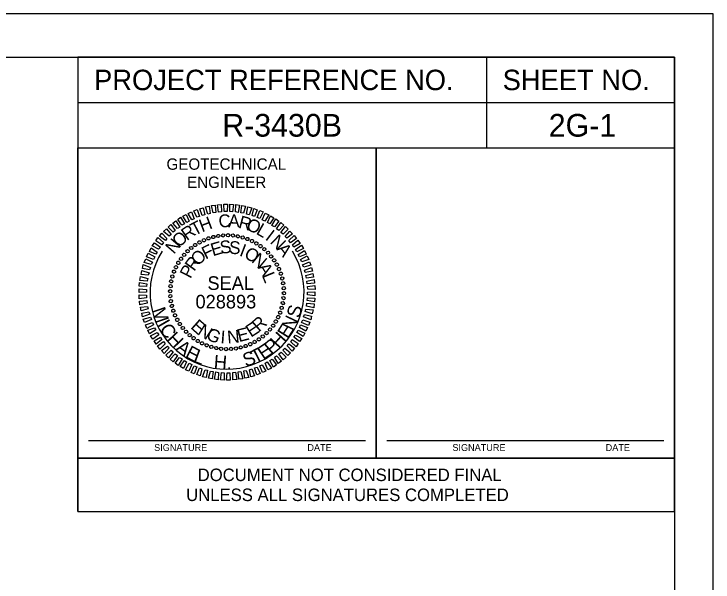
# Model space of a CAD drawing. Extents: x 1252282 to 1252638, y 733735 to 733845.
# Drawn here: x 1252606.82 to 1252637.98, y 733819.19 to 733844.5 of the extents above; entities that cross this region are included whole.
import ezdxf

# ---------------------------------------------------------------- set-up
doc = ezdxf.new("R2010")
doc.units = 0
for name, color, linetype in [('Default', 7, 'Continuous'), ('Scratch_Level_0', 7, 'Continuous'), ('Sheet Plot Border Outside CELL', 7, 'Continuous'), ('Sheet Professional Seal CELL', 7, 'Continuous'), ('Sheet Sticker Exception Certification CELL', 7, 'Continuous'), ('Sheet Typical CELL', 7, 'Continuous')]:
    doc.layers.add(name, color=color, linetype=linetype)

msp = doc.modelspace()

# ---------------------------------------------------------------- linework, layer by layer
at = {"layer": 'Scratch_Level_0'}
msp.add_line((1252637.975, 733844.502), (1252637.975, 733844.502), dxfattribs=at)
msp.add_ellipse((1252616.319, 733832.107), major_axis=(2.279, 2.58), ratio=0.993455, start_param=1.731198, end_param=5.992706, dxfattribs=at)
at = {"layer": 'Sheet Plot Border Outside CELL'}
msp.add_lwpolyline([(1252467.333, 733734.502), (1252637.975, 733734.502), (1252637.975, 733844.502), (1252467.333, 733844.502)], close=True, dxfattribs=at)
at = {"layer": 'Sheet Professional Seal CELL'}
for p, q in [((1252615.288, 733834.427), (1252615.288, 733834.427)), ((1252615.49, 733834.507), (1252615.49, 733834.507)), ((1252615.702, 733834.568), (1252615.702, 733834.568)), ((1252615.925, 733834.609), (1252615.925, 733834.609)), ((1252616.142, 733834.639), (1252616.142, 733834.639)), ((1252616.364, 733834.644), (1252616.364, 733834.644)), ((1252616.587, 733834.629), (1252616.587, 733834.629)), ((1252616.804, 733834.593), (1252616.804, 733834.593)), ((1252617.016, 733834.548), (1252617.016, 733834.548)), ((1252617.229, 733834.477), (1252617.229, 733834.477)), ((1252617.431, 733834.386), (1252617.431, 733834.386)), ((1252614.722, 733834.083), (1252614.722, 733834.083)), ((1252614.898, 733834.209), (1252614.898, 733834.209)), ((1252615.091, 733834.326), (1252615.091, 733834.326)), ((1252617.628, 733834.285), (1252617.628, 733834.285)), ((1252617.81, 733834.159), (1252617.81, 733834.159)), ((1252614.403, 733833.775), (1252614.403, 733833.775)), ((1252614.555, 733833.931), (1252614.555, 733833.931)), ((1252617.987, 733834.022), (1252617.987, 733834.022)), ((1252618.143, 733833.871), (1252618.143, 733833.871)), ((1252614.267, 733833.598), (1252614.267, 733833.598)), ((1252618.295, 733833.704), (1252618.295, 733833.704)), ((1252618.421, 733833.527), (1252618.421, 733833.527)), ((1252614.039, 733833.219), (1252614.039, 733833.219)), ((1252614.14, 733833.416), (1252614.14, 733833.416)), ((1252618.538, 733833.335), (1252618.538, 733833.335)), ((1252618.639, 733833.138), (1252618.639, 733833.138)), ((1252613.877, 733832.804), (1252613.877, 733832.804)), ((1252613.948, 733833.016), (1252613.948, 733833.016)), ((1252618.72, 733832.936), (1252618.72, 733832.936)), ((1252613.832, 733832.592), (1252613.832, 733832.592)), ((1252618.78, 733832.723), (1252618.78, 733832.723)), ((1252618.821, 733832.501), (1252618.821, 733832.501)), ((1252613.797, 733832.374), (1252613.797, 733832.374)), ((1252618.851, 733832.283), (1252618.851, 733832.283)), ((1252613.781, 733832.152), (1252613.781, 733832.152)), ((1252613.786, 733831.93), (1252613.786, 733831.93)), ((1252618.856, 733832.061), (1252618.856, 733832.061)), ((1252613.817, 733831.712), (1252613.817, 733831.712)), ((1252618.806, 733831.621), (1252618.806, 733831.621)), ((1252618.841, 733831.839), (1252618.841, 733831.839)), ((1252613.857, 733831.49), (1252613.857, 733831.49)), ((1252613.918, 733831.278), (1252613.918, 733831.278)), ((1252618.76, 733831.409), (1252618.76, 733831.409)), ((1252613.999, 733831.075), (1252613.999, 733831.075)), ((1252618.598, 733830.995), (1252618.598, 733830.995)), ((1252618.689, 733831.197), (1252618.689, 733831.197)), ((1252614.1, 733830.878), (1252614.1, 733830.878)), ((1252614.216, 733830.686), (1252614.216, 733830.686)), ((1252618.497, 733830.797), (1252618.497, 733830.797)), ((1252614.342, 733830.509), (1252614.342, 733830.509)), ((1252614.494, 733830.343), (1252614.494, 733830.343)), ((1252618.234, 733830.439), (1252618.234, 733830.439)), ((1252618.371, 733830.615), (1252618.371, 733830.615)), ((1252614.651, 733830.191), (1252614.651, 733830.191)), ((1252614.828, 733830.054), (1252614.828, 733830.054)), ((1252617.739, 733830.004), (1252617.739, 733830.004)), ((1252617.916, 733830.13), (1252617.916, 733830.13)), ((1252618.083, 733830.282), (1252618.083, 733830.282)), ((1252615.01, 733829.928), (1252615.01, 733829.928)), ((1252615.207, 733829.827), (1252615.207, 733829.827)), ((1252615.409, 733829.736), (1252615.409, 733829.736)), ((1252617.148, 733829.706), (1252617.148, 733829.706)), ((1252617.35, 733829.787), (1252617.35, 733829.787)), ((1252617.547, 733829.888), (1252617.547, 733829.888)), ((1252615.621, 733829.665), (1252615.621, 733829.665)), ((1252615.834, 733829.62), (1252615.834, 733829.62)), ((1252616.051, 733829.584), (1252616.051, 733829.584)), ((1252616.273, 733829.569), (1252616.273, 733829.569)), ((1252616.496, 733829.574), (1252616.496, 733829.574)), ((1252616.713, 733829.605), (1252616.713, 733829.605)), ((1252616.935, 733829.645), (1252616.935, 733829.645))]:
    msp.add_line(p, q, dxfattribs=at)
for points in [[(1252615.459, 733835.589), (1252615.353, 733835.908), (1252615.525, 733835.943), (1252615.566, 733835.614)], [(1252615.702, 733835.645), (1252615.621, 733835.968), (1252615.788, 733835.983), (1252615.823, 733835.66)], [(1252615.945, 733835.675), (1252615.889, 733835.999), (1252616.061, 733836.019), (1252616.066, 733835.69)], [(1252616.197, 733835.7), (1252616.172, 733836.029), (1252616.339, 733836.024), (1252616.319, 733835.695)], [(1252616.44, 733835.695), (1252616.44, 733836.024), (1252616.607, 733836.019), (1252616.561, 733835.69)], [(1252616.693, 733835.68), (1252616.713, 733836.009), (1252616.88, 733835.978), (1252616.814, 733835.66)], [(1252616.935, 733835.64), (1252616.981, 733835.963), (1252617.148, 733835.938), (1252617.057, 733835.625)], [(1252617.193, 733835.584), (1252617.244, 733835.913), (1252617.416, 733835.872), (1252617.299, 733835.559)], [(1252614.747, 733835.336), (1252614.585, 733835.619), (1252614.742, 733835.69), (1252614.858, 733835.382)], [(1252614.969, 733835.443), (1252614.838, 733835.736), (1252614.989, 733835.796), (1252615.096, 733835.473)], [(1252615.217, 733835.523), (1252615.101, 733835.827), (1252615.257, 733835.872), (1252615.323, 733835.559)], [(1252617.436, 733835.518), (1252617.512, 733835.832), (1252617.668, 733835.781), (1252617.542, 733835.483)], [(1252617.663, 733835.427), (1252617.78, 733835.746), (1252617.921, 733835.685), (1252617.78, 733835.392)], [(1252617.891, 733835.331), (1252618.017, 733835.63), (1252618.174, 733835.559), (1252618.002, 733835.276)], [(1252614.307, 733835.089), (1252614.12, 733835.347), (1252614.251, 733835.443), (1252614.418, 733835.149)], [(1252614.529, 733835.215), (1252614.342, 733835.488), (1252614.499, 733835.569), (1252614.625, 733835.276)], [(1252618.123, 733835.215), (1252618.26, 733835.503), (1252618.411, 733835.417), (1252618.219, 733835.154)], [(1252618.32, 733835.079), (1252618.497, 733835.372), (1252618.629, 733835.266), (1252618.432, 733835.018)], [(1252613.913, 733834.78), (1252613.69, 733835.003), (1252613.812, 733835.124), (1252614.009, 733834.851)], [(1252614.115, 733834.937), (1252613.898, 733835.18), (1252614.034, 733835.286), (1252614.211, 733835.003)], [(1252618.528, 733834.927), (1252618.715, 733835.205), (1252618.846, 733835.094), (1252618.624, 733834.856)], [(1252618.72, 733834.77), (1252618.927, 733835.033), (1252619.048, 733834.912), (1252618.816, 733834.694)], [(1252613.569, 733834.411), (1252613.306, 733834.609), (1252613.417, 733834.74), (1252613.64, 733834.502)], [(1252613.746, 733834.604), (1252613.488, 733834.811), (1252613.615, 733834.927), (1252613.827, 733834.684)], [(1252618.902, 733834.593), (1252619.119, 733834.831), (1252619.24, 733834.71), (1252618.977, 733834.513)], [(1252613.417, 733834.219), (1252613.144, 733834.391), (1252613.241, 733834.538), (1252613.483, 733834.315)], [(1252619.079, 733834.411), (1252619.311, 733834.639), (1252619.417, 733834.502), (1252619.149, 733834.31)], [(1252619.23, 733834.214), (1252619.478, 733834.427), (1252619.574, 733834.28), (1252619.291, 733834.118)], [(1252613.144, 733833.8), (1252612.856, 733833.926), (1252612.932, 733834.083), (1252613.205, 733833.896)], [(1252613.266, 733834.017), (1252612.983, 733834.169), (1252613.084, 733834.31), (1252613.347, 733834.108)], [(1252619.362, 733834.007), (1252619.63, 733834.199), (1252619.726, 733834.048), (1252619.432, 733833.906)], [(1252613.043, 733833.567), (1252612.73, 733833.684), (1252612.806, 733833.84), (1252613.094, 733833.679)], [(1252619.493, 733833.785), (1252619.776, 733833.962), (1252619.842, 733833.805), (1252619.554, 733833.689)], [(1252612.942, 733833.345), (1252612.629, 733833.436), (1252612.695, 733833.593), (1252612.998, 733833.451)], [(1252619.594, 733833.567), (1252619.892, 733833.719), (1252619.958, 733833.557), (1252619.645, 733833.456)], [(1252619.685, 733833.33), (1252619.993, 733833.461), (1252620.049, 733833.304), (1252619.736, 733833.224)], [(1252612.866, 733833.102), (1252612.553, 733833.168), (1252612.588, 733833.335), (1252612.907, 733833.208)], [(1252619.766, 733833.087), (1252620.089, 733833.203), (1252620.12, 733833.037), (1252619.801, 733832.981)], [(1252612.76, 733832.602), (1252612.437, 733832.632), (1252612.457, 733832.804), (1252612.786, 733832.723)], [(1252612.801, 733832.86), (1252612.487, 733832.9), (1252612.523, 733833.072), (1252612.841, 733832.966)], [(1252619.827, 733832.845), (1252620.145, 733832.941), (1252620.175, 733832.769), (1252619.857, 733832.738)], [(1252612.735, 733832.359), (1252612.407, 733832.369), (1252612.417, 733832.536), (1252612.745, 733832.481)], [(1252619.872, 733832.602), (1252620.201, 733832.673), (1252620.216, 733832.501), (1252619.892, 733832.481)], [(1252612.73, 733832.107), (1252612.401, 733832.091), (1252612.401, 733832.263), (1252612.73, 733832.228)], [(1252619.902, 733832.359), (1252620.231, 733832.4), (1252620.241, 733832.228), (1252619.913, 733832.238)], [(1252612.735, 733831.854), (1252612.407, 733831.813), (1252612.396, 733831.985), (1252612.725, 733831.975)], [(1252619.908, 733832.107), (1252620.236, 733832.122), (1252620.236, 733831.95), (1252619.908, 733831.985)], [(1252612.765, 733831.611), (1252612.437, 733831.54), (1252612.422, 733831.712), (1252612.745, 733831.733)], [(1252619.877, 733831.611), (1252620.201, 733831.581), (1252620.18, 733831.409), (1252619.852, 733831.49)], [(1252619.902, 733831.854), (1252620.231, 733831.844), (1252620.221, 733831.677), (1252619.892, 733831.733)], [(1252612.811, 733831.369), (1252612.492, 733831.273), (1252612.462, 733831.444), (1252612.781, 733831.475)], [(1252619.837, 733831.353), (1252620.15, 733831.313), (1252620.115, 733831.141), (1252619.796, 733831.247)], [(1252612.872, 733831.126), (1252612.548, 733831.01), (1252612.518, 733831.177), (1252612.836, 733831.232)], [(1252612.952, 733830.883), (1252612.644, 733830.752), (1252612.588, 733830.909), (1252612.902, 733830.989)], [(1252619.771, 733831.111), (1252620.084, 733831.045), (1252620.049, 733830.878), (1252619.731, 733831.005)], [(1252613.043, 733830.646), (1252612.745, 733830.494), (1252612.679, 733830.656), (1252612.993, 733830.757)], [(1252619.594, 733830.646), (1252619.908, 733830.53), (1252619.832, 733830.373), (1252619.544, 733830.535)], [(1252619.695, 733830.868), (1252620.009, 733830.777), (1252619.943, 733830.621), (1252619.64, 733830.762)], [(1252613.144, 733830.428), (1252612.861, 733830.252), (1252612.796, 733830.408), (1252613.084, 733830.524)], [(1252613.276, 733830.206), (1252613.008, 733830.014), (1252612.912, 733830.166), (1252613.205, 733830.307)], [(1252619.493, 733830.413), (1252619.781, 733830.287), (1252619.705, 733830.13), (1252619.432, 733830.317)], [(1252613.407, 733829.999), (1252613.16, 733829.787), (1252613.064, 733829.933), (1252613.347, 733830.095)], [(1252619.22, 733829.994), (1252619.493, 733829.822), (1252619.397, 733829.675), (1252619.154, 733829.898)], [(1252619.372, 733830.196), (1252619.655, 733830.044), (1252619.554, 733829.903), (1252619.291, 733830.105)], [(1252613.559, 733829.802), (1252613.326, 733829.574), (1252613.22, 733829.711), (1252613.488, 733829.903)], [(1252613.736, 733829.62), (1252613.519, 733829.382), (1252613.397, 733829.503), (1252613.66, 733829.701)], [(1252619.068, 733829.802), (1252619.331, 733829.605), (1252619.22, 733829.473), (1252618.998, 733829.711)], [(1252613.918, 733829.443), (1252613.711, 733829.18), (1252613.589, 733829.301), (1252613.822, 733829.519)], [(1252618.725, 733829.433), (1252618.947, 733829.21), (1252618.826, 733829.089), (1252618.629, 733829.362)], [(1252618.892, 733829.61), (1252619.149, 733829.402), (1252619.023, 733829.286), (1252618.811, 733829.529)], [(1252614.11, 733829.286), (1252613.923, 733829.008), (1252613.791, 733829.119), (1252614.014, 733829.357)], [(1252614.317, 733829.134), (1252614.14, 733828.841), (1252614.009, 733828.947), (1252614.206, 733829.195)], [(1252618.33, 733829.124), (1252618.518, 733828.867), (1252618.386, 733828.771), (1252618.219, 733829.064)], [(1252618.523, 733829.276), (1252618.74, 733829.033), (1252618.603, 733828.927), (1252618.427, 733829.21)], [(1252614.514, 733828.998), (1252614.378, 733828.71), (1252614.226, 733828.796), (1252614.418, 733829.059)], [(1252614.747, 733828.882), (1252614.62, 733828.584), (1252614.464, 733828.654), (1252614.636, 733828.937)], [(1252614.974, 733828.786), (1252614.858, 733828.467), (1252614.716, 733828.528), (1252614.858, 733828.821)], [(1252617.668, 733828.771), (1252617.8, 733828.477), (1252617.648, 733828.417), (1252617.542, 733828.74)], [(1252617.891, 733828.877), (1252618.052, 733828.594), (1252617.896, 733828.523), (1252617.78, 733828.831)], [(1252618.108, 733828.998), (1252618.295, 733828.725), (1252618.138, 733828.644), (1252618.012, 733828.937)], [(1252615.202, 733828.695), (1252615.126, 733828.381), (1252614.969, 733828.432), (1252615.096, 733828.73)], [(1252615.444, 733828.629), (1252615.394, 733828.3), (1252615.222, 733828.341), (1252615.338, 733828.654)], [(1252615.702, 733828.573), (1252615.657, 733828.25), (1252615.49, 733828.275), (1252615.581, 733828.589)], [(1252615.945, 733828.533), (1252615.925, 733828.204), (1252615.758, 733828.235), (1252615.823, 733828.553)], [(1252616.197, 733828.518), (1252616.197, 733828.189), (1252616.031, 733828.194), (1252616.076, 733828.523)], [(1252616.44, 733828.513), (1252616.465, 733828.184), (1252616.299, 733828.189), (1252616.319, 733828.518)], [(1252616.693, 733828.538), (1252616.748, 733828.215), (1252616.577, 733828.194), (1252616.571, 733828.523)], [(1252616.935, 733828.568), (1252617.016, 733828.245), (1252616.849, 733828.23), (1252616.814, 733828.553)], [(1252617.178, 733828.624), (1252617.284, 733828.306), (1252617.112, 733828.27), (1252617.072, 733828.599)], [(1252617.421, 733828.69), (1252617.537, 733828.386), (1252617.38, 733828.341), (1252617.315, 733828.654)]]:
    msp.add_lwpolyline(points, close=True, dxfattribs=at)
for centre, major_axis in [((1252615.922, 733834.611), (-0.0114, 0.0719)), ((1252616.142, 733834.636), (-0.0051, 0.0726)), ((1252616.363, 733834.642), (0.0013, 0.0728)), ((1252616.584, 733834.628), (0.0076, 0.0724)), ((1252616.803, 733834.595), (0.0139, 0.0714)), ((1252615.09, 733834.324), (-0.0353, 0.0637)), ((1252615.288, 733834.423), (-0.0296, 0.0665)), ((1252615.493, 733834.504), (-0.0237, 0.0688)), ((1252615.705, 733834.567), (-0.0176, 0.0706)), ((1252617.018, 733834.544), (0.0201, 0.07)), ((1252617.227, 733834.474), (0.0261, 0.068)), ((1252617.43, 733834.385), (0.0319, 0.0654)), ((1252617.625, 733834.28), (0.0375, 0.0624)), ((1252614.723, 733834.077), (-0.0458, 0.0566)), ((1252614.901, 733834.208), (-0.0407, 0.0603)), ((1252617.809, 733834.158), (0.0428, 0.0589)), ((1252617.982, 733834.02), (0.0478, 0.0549)), ((1252614.405, 733833.77), (-0.0549, 0.0478)), ((1252614.558, 733833.93), (-0.0506, 0.0524)), ((1252618.143, 733833.868), (0.0524, 0.0506)), ((1252618.289, 733833.702), (0.0566, 0.0458)), ((1252614.146, 733833.412), (-0.0624, 0.0375)), ((1252614.268, 733833.597), (-0.0589, 0.0428)), ((1252618.421, 733833.524), (0.0603, 0.0407)), ((1252614.04, 733833.218), (-0.0654, 0.0319)), ((1252618.536, 733833.336), (0.0637, 0.0353)), ((1252618.635, 733833.138), (0.0665, 0.0296)), ((1252613.882, 733832.805), (-0.07, 0.0201)), ((1252613.952, 733833.015), (-0.068, 0.0261)), ((1252618.716, 733832.932), (0.0688, 0.0237)), ((1252618.779, 733832.72), (0.0706, 0.0176)), ((1252613.83, 733832.59), (-0.0714, 0.0139)), ((1252618.823, 733832.503), (0.0719, 0.0114)), ((1252613.784, 733832.151), (-0.0728, 0.0013)), ((1252613.797, 733832.372), (-0.0724, 0.0076)), ((1252618.848, 733832.283), (0.0726, 0.0051)), ((1252613.79, 733831.93), (-0.0726, -0.0051)), ((1252618.84, 733831.842), (0.0724, -0.0076)), ((1252618.854, 733832.062), (0.0728, -0.0013)), ((1252613.815, 733831.71), (-0.0719, -0.0114)), ((1252613.859, 733831.493), (-0.0706, -0.0176)), ((1252618.808, 733831.623), (0.0714, -0.0139)), ((1252613.922, 733831.281), (-0.0688, -0.0237)), ((1252618.686, 733831.198), (0.068, -0.0261)), ((1252618.756, 733831.408), (0.07, -0.0201)), ((1252614.003, 733831.075), (-0.0665, -0.0296)), ((1252614.101, 733830.877), (-0.0637, -0.0353)), ((1252618.598, 733830.995), (0.0654, -0.0319)), ((1252614.217, 733830.689), (-0.0603, -0.0407)), ((1252618.37, 733830.616), (0.0589, -0.0428)), ((1252618.492, 733830.801), (0.0624, -0.0375)), ((1252614.348, 733830.511), (-0.0566, -0.0458)), ((1252614.495, 733830.345), (-0.0524, -0.0506)), ((1252618.08, 733830.283), (0.0506, -0.0524)), ((1252618.232, 733830.443), (0.0549, -0.0478)), ((1252614.655, 733830.193), (-0.0478, -0.0549)), ((1252614.829, 733830.055), (-0.0428, -0.0589)), ((1252615.013, 733829.933), (-0.0375, -0.0624)), ((1252617.737, 733830.005), (0.0407, -0.0603)), ((1252617.914, 733830.136), (0.0458, -0.0566)), ((1252615.207, 733829.828), (-0.0319, -0.0654)), ((1252615.41, 733829.74), (-0.0261, -0.068)), ((1252615.62, 733829.669), (-0.0201, -0.07)), ((1252615.835, 733829.618), (-0.0139, -0.0714)), ((1252616.932, 733829.646), (0.0176, -0.0706)), ((1252617.144, 733829.709), (0.0237, -0.0688)), ((1252617.35, 733829.79), (0.0296, -0.0665)), ((1252617.548, 733829.889), (0.0353, -0.0637)), ((1252616.054, 733829.585), (-0.0076, -0.0724)), ((1252616.275, 733829.572), (-0.0013, -0.0728)), ((1252616.496, 733829.577), (0.0051, -0.0726)), ((1252616.715, 733829.602), (0.0114, -0.0719))]:
    msp.add_ellipse(centre, major_axis=major_axis, ratio=0.999708, dxfattribs=at)
at = {"layer": 'Sheet Sticker Exception Certification CELL'}
for p, q in [((1252609.673, 733822.335), (1252609.673, 733824.711)), ((1252609.673, 733824.711), (1252636.257, 733824.711)), ((1252636.257, 733824.711), (1252636.257, 733822.335)), ((1252609.673, 733822.335), (1252636.257, 733822.335))]:
    msp.add_line(p, q, dxfattribs=at)
at = {"layer": 'Sheet Typical CELL'}
for p, q in [((1252627.881, 733842.575), (1252627.88, 733838.532)), ((1252609.673, 733840.553), (1252636.257, 733840.553)), ((1252622.496, 733825.489), (1252610.142, 733825.489)), ((1252635.788, 733825.489), (1252623.433, 733825.489))]:
    msp.add_line(p, q, dxfattribs=at)
for points in [[(1252484.62, 733842.575), (1252636.257, 733842.575), (1252636.257, 733736.429), (1252484.62, 733736.429)], [(1252609.673, 733838.532), (1252636.257, 733838.532), (1252636.257, 733842.575), (1252609.673, 733842.575)], [(1252609.673, 733822.335), (1252636.257, 733822.335), (1252636.257, 733842.575), (1252609.673, 733842.575)], [(1252609.673, 733838.532), (1252622.965, 733838.532), (1252622.965, 733824.711), (1252609.673, 733824.711)], [(1252622.965, 733838.532), (1252636.257, 733838.532), (1252636.257, 733824.711), (1252622.965, 733824.711)]]:
    msp.add_lwpolyline(points, close=True, dxfattribs=at)

# ---------------------------------------------------------------- texts
at = {"layer": 'Default'}
for s, p in [('R-3430B', (1252616.105, 733839.037)), ('2G-1', (1252630.654, 733839.037))]:
    msp.add_text(s, height=1.0109, dxfattribs=at).set_placement(p)
at = {"layer": 'Sheet Professional Seal CELL'}
for s, height, rotation, p in [('T', 0.57, 27.8198, (1252614.873, 733834.604)), ('H', 0.57, 20.6195, (1252615.202, 733834.77)), ('C', 0.57, 6.2199, (1252615.97, 733834.972)), ('A', 0.57, 359.0203, (1252616.369, 733835.003)), ('R', 0.57, 344.6211, (1252616.794, 733834.983)), ('O', 0.57, 337.4212, (1252617.133, 733834.907)), ('R', 0.57, 35.0205, (1252614.529, 733834.381)), ('L', 0.57, 330.2209, (1252617.577, 733834.72)), ('O', 0.57, 42.2217, (1252614.181, 733834.068)), ('I', 0.57, 323.0201, (1252617.987, 733834.477)), ('N', 0.57, 315.8189, (1252618.204, 733834.32)), ('N', 0.57, 49.4235, (1252613.948, 733833.775)), ('E', 0.57, 16.6111, (1252615.687, 733833.704)), ('S', 0.57, 7.2556, (1252616.036, 733833.81)), ('S', 0.57, 357.9004, (1252616.4, 733833.815)), ('F', 0.57, 25.967, (1252615.363, 733833.552)), ('I', 0.57, 339.1896, (1252616.834, 733833.744)), ('O', 0.57, 329.8335, (1252617.037, 733833.673)), ('A', 0.57, 308.6172, (1252618.502, 733834.022)), ('O', 0.57, 44.6812, (1252615.03, 733833.254)), ('N', 0.57, 320.4766, (1252617.375, 733833.471)), ('R', 0.57, 54.0397, (1252614.853, 733833.006)), ('P', 0.57, 63.3989, (1252614.691, 733832.683)), ('A', 0.57, 301.7603, (1252617.663, 733833.208)), ('L', 0.57, 292.4008, (1252617.86, 733832.86)), ('M', 0.606, 288.6045, (1252612.959, 733831.317)), ('S', 0.606, 75.2858, (1252619.548, 733830.923)), ('R', 0.57, 42.4814, (1252617.744, 733830.312)), ('N', 0.606, 64.7114, (1252619.271, 733830.346)), ('I', 0.606, 300.1279, (1252613.178, 733830.665)), ('C', 0.606, 303.9345, (1252613.279, 733830.461)), ('E', 0.57, 318.2769, (1252614.661, 733830.524)), ('N', 0.57, 327.634, (1252614.964, 733830.252)), ('E', 0.57, 33.1241, (1252617.385, 733830.075)), ('E', 0.606, 57.7144, (1252619.031, 733829.996)), ('H', 0.606, 313.5376, (1252613.59, 733829.981)), ('G', 0.57, 336.9902, (1252615.348, 733830.024)), ('I', 0.57, 355.7012, (1252616.01, 733829.832)), ('N', 0.57, 5.0564, (1252616.349, 733829.817)), ('E', 0.57, 14.4118, (1252616.849, 733829.877)), ('H', 0.606, 47.8962, (1252618.626, 733829.559)), ('P', 0.606, 40.9051, (1252618.295, 733829.293)), ('A', 0.606, 323.5491, (1252613.995, 733829.544)), ('E', 0.606, 332.4092, (1252614.412, 733829.221)), ('E', 0.606, 33.9096, (1252617.934, 733829.07)), ('L', 0.606, 339.5258, (1252614.781, 733829.01)), ('S', 0.606, 19.9821, (1252617.149, 733828.764)), ('T', 0.606, 27.2105, (1252617.565, 733828.899)), ('H', 0.606, 355.9689, (1252615.714, 733828.707)), ('.', 0.606, 5.8919, (1252616.308, 733828.657))]:
    msp.add_text(s, height=height, rotation=rotation, dxfattribs=at).set_placement(p)
for s, p in [('SEAL', (1252615.445, 733832.208)), ('028893', (1252614.913, 733831.383))]:
    msp.add_text(s, height=0.6064, dxfattribs=at).set_placement(p)
at = {"layer": 'Sheet Sticker Exception Certification CELL'}
for s, p in [('DOCUMENT NOT CONSIDERED FINAL', (1252615.009, 733823.69)), ('UNLESS ALL SIGNATURES COMPLETED', (1252614.496, 733822.8))]:
    msp.add_text(s, height=0.556, dxfattribs=at).set_placement(p)
at = {"layer": 'Sheet Typical CELL'}
for s, height, p in [('PROJECT REFERENCE NO.', 0.90982, (1252610.393, 733841.109)), ('SHEET NO.', 0.9098, (1252628.601, 733841.109)), ('GEOTECHNICAL', 0.50546, (1252613.62, 733837.561)), ('ENGINEER', 0.5055, (1252614.536, 733836.752)), ('SIGNATURE', 0.3033, (1252613.07, 733825.033)), ('DATE', 0.3033, (1252619.899, 733825.033)), ('SIGNATURE', 0.3033, (1252626.361, 733825.033)), ('DATE', 0.3033, (1252633.191, 733825.033))]:
    msp.add_text(s, height=height, dxfattribs=at).set_placement(p)

doc.saveas('drawing.dxf')
